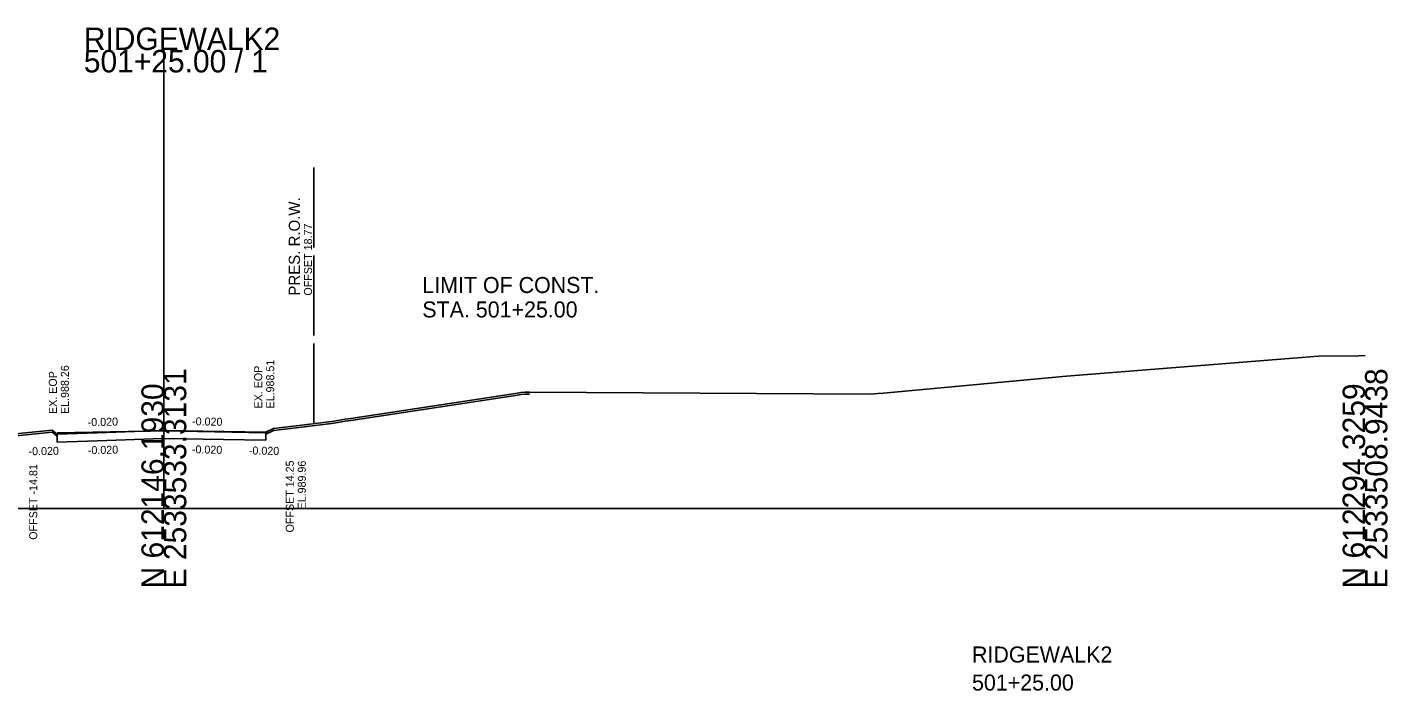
# Model space of a CAD drawing. Extents: x -26 to 303, y -23 to 1542.
# Drawn here: x 132.8 to 302.8, y 977.2 to 1060.1 of the extents above; entities that cross this region are included whole.
import ezdxf

# ---------------------------------------------------------------- set-up
doc = ezdxf.new("R2010")
doc.units = 0
for name, color, linetype in [('DESIGN - SHEET - Light Grid', 7, 'Continuous'), ('DESIGN - TRANSPORTATION - Proposed Layout Patterning', 7, 'Continuous'), ('DESIGN - TRANSPORTATION - Text', 7, 'Continuous'), ('DESIGN - TYPICAL - Finished Grade Slopes Text', 7, 'Continuous'), ('DESIGN - TYPICAL - Subgrade Cross Slope Text', 7, 'Continuous'), ('DESIGN - TYPICAL - Subgrade Tie Text', 7, 'Continuous'), ('DESIGN - TYPICAL - Warning Text', 7, 'Continuous'), ('SURVEY - GROUND - Bottom of Topsoil Layer', 7, 'Continuous'), ('SURVEY - GROUND - Existing Pavement Layer', 7, 'Continuous'), ('SURVEY - GROUND - Existing Pavement Text', 7, 'Continuous'), ('SURVEY - GROUND - Top of Ground', 7, 'Continuous'), ('SURVEY - PROPERTY - ROW Lines', 7, 'Continuous'), ('SURVEY - PROPERTY - ROW Lines Text', 7, 'Continuous')]:
    doc.layers.add(name, color=color, linetype=linetype)

msp = doc.modelspace()

# ---------------------------------------------------------------- linework, layer by layer
at = {"layer": 'DESIGN - SHEET - Light Grid'}
for p, q in [((149.88, 1000), (149.88, 1057.24)), ((0, 1000), (149.88, 1000)), ((149.88, 1000), (300, 1000))]:
    msp.add_line(p, q, dxfattribs=at)
at = {"layer": 'DESIGN - TRANSPORTATION - Proposed Layout Patterning'}
for q in [(136.56, 1009.44), (162.62, 1009.45)]:
    msp.add_line((149.88, 1009.7), q, dxfattribs=at)
at = {"layer": 'SURVEY - GROUND - Bottom of Topsoil Layer'}
for p, q in [((173.25, 1010.98), (193.81, 1014.11)), ((193.81, 1014.11), (194.51, 1014.22)), ((194.51, 1014.22), (195.05, 1014.28)), ((195.05, 1014.28), (195.56, 1014.27)), ((163.59, 1009.73), (167.13, 1010.12)), ((167.13, 1010.12), (171.16, 1010.64)), ((171.16, 1010.64), (172.52, 1010.87)), ((172.52, 1010.87), (172.93, 1010.94)), ((172.93, 1010.94), (173.25, 1010.98)), ((127.12, 1008.63), (135.91, 1009.5)), ((135.91, 1009.5), (136.56, 1009.01)), ((136.56, 1009.01), (136.56, 1009.26)), ((162.62, 1009.26), (163.59, 1009.73)), ((162.62, 1009.26), (162.62, 1009.51))]:
    msp.add_line(p, q, dxfattribs=at)
at = {"layer": 'SURVEY - GROUND - Existing Pavement Layer'}
for p, q in [((136.56, 1009.26), (136.56, 1008.26)), ((162.62, 1009.51), (162.62, 1008.51))]:
    msp.add_line(p, q, dxfattribs=at)
msp.add_lwpolyline([(136.56, 1008.26), (141.59, 1008.43), (149.73, 1008.71), (157.34, 1008.6), (162.62, 1008.51)], dxfattribs=at)
at = {"layer": 'SURVEY - GROUND - Top of Ground'}
for p, q in [((262.7, 1016.52), (294.16, 1018.99)), ((195.56, 1014.52), (238.14, 1014.25))]:
    msp.add_line(p, q, dxfattribs=at)
for points in [[(294.16, 1018.99), (299.21, 1019.06), (300, 1019.08)], [(238.14, 1014.25), (238.65, 1014.3), (239.17, 1014.34), (239.81, 1014.4), (262.7, 1016.52)], [(127.12, 1008.88), (135.91, 1009.75), (136.56, 1009.26), (141.55, 1009.43), (149.72, 1009.71), (157.36, 1009.6), (162.62, 1009.51), (163.59, 1009.98), (167.13, 1010.37), (171.16, 1010.89), (172.52, 1011.12), (172.93, 1011.19), (173.25, 1011.23), (193.81, 1014.36), (194.51, 1014.47), (195.05, 1014.53), (195.56, 1014.52)]]:
    msp.add_lwpolyline(points, dxfattribs=at)
at = {"layer": 'SURVEY - PROPERTY - ROW Lines'}
for p, q in [((168.64, 1032.57), (168.64, 1042.57)), ((168.64, 1021.57), (168.64, 1031.57)), ((168.64, 1010.57), (168.64, 1020.57))]:
    msp.add_line(p, q, dxfattribs=at)

# ---------------------------------------------------------------- texts
at = {"layer": 'DESIGN - SHEET - Light Grid'}
for s, p in [('RIDGEWALK2', (139.88, 1057.24)), ('501+25.00 / 1', (139.88, 1054.44))]:
    msp.add_text(s, height=2.8, dxfattribs=at).set_placement(p)
for s, p in [('E 2533533.3131', (152.68, 990)), ('E 2533508.9438', (302.8, 990)), ('N 612146.1930', (149.88, 990)), ('N 612294.3259', (300, 990))]:
    msp.add_text(s, height=2.8, rotation=90, dxfattribs=at).set_placement(p)
at = {"layer": 'DESIGN - TRANSPORTATION - Text'}
for s, p in [('LIMIT OF CONST.', (182.18, 1026.89)), ('STA. 501+25.00', (182.18, 1023.84))]:
    msp.add_text(s, height=2, dxfattribs=at).set_placement(p)
at = {"layer": 'DESIGN - TYPICAL - Finished Grade Slopes Text'}
for rotation, p in [(1.1458, (140.37, 1010.26)), (358.8542, (153.4, 1010.38))]:
    msp.add_text('-0.020', height=1, rotation=rotation, dxfattribs=at).set_placement(p)
at = {"layer": 'DESIGN - TYPICAL - Subgrade Cross Slope Text'}
for rotation, p in [(1.1458, (132.98, 1006.62)), (1.1458, (140.39, 1006.76)), (358.8542, (153.38, 1006.88)), (358.8542, (160.5, 1006.74))]:
    msp.add_text('-0.020', height=1, rotation=rotation, dxfattribs=at).set_placement(p)
at = {"layer": 'DESIGN - TYPICAL - Subgrade Tie Text'}
for s, p in [('OFFSET -14.81', (134.06, 996.08)), ('OFFSET 14.25', (166.12, 996.99)), ('EL.989.96', (167.62, 999.86))]:
    msp.add_text(s, height=1, rotation=90, dxfattribs=at).set_placement(p)
at = {"layer": 'DESIGN - TYPICAL - Warning Text'}
for s, p in [('RIDGEWALK2', (250.88, 980.75)), ('501+25.00', (250.88, 977.25))]:
    msp.add_text(s, height=2, dxfattribs=at).set_placement(p)
at = {"layer": 'SURVEY - GROUND - Existing Pavement Text'}
for s, p in [('EX. EOP', (136.51, 1011.78)), ('EL.988.26', (138.01, 1011.78)), ('EX. EOP', (162.17, 1012.47)), ('EL.988.51', (163.67, 1012.47))]:
    msp.add_text(s, height=1, rotation=90, dxfattribs=at).set_placement(p)
at = {"layer": 'SURVEY - PROPERTY - ROW Lines Text'}
for s, height, p in [('PRES. R.O.W.', 1.4, (166.89, 1026.57)), ('OFFSET 18.77', 1, (168.39, 1026.57))]:
    msp.add_text(s, height=height, rotation=90, dxfattribs=at).set_placement(p)

doc.saveas('drawing.dxf')
